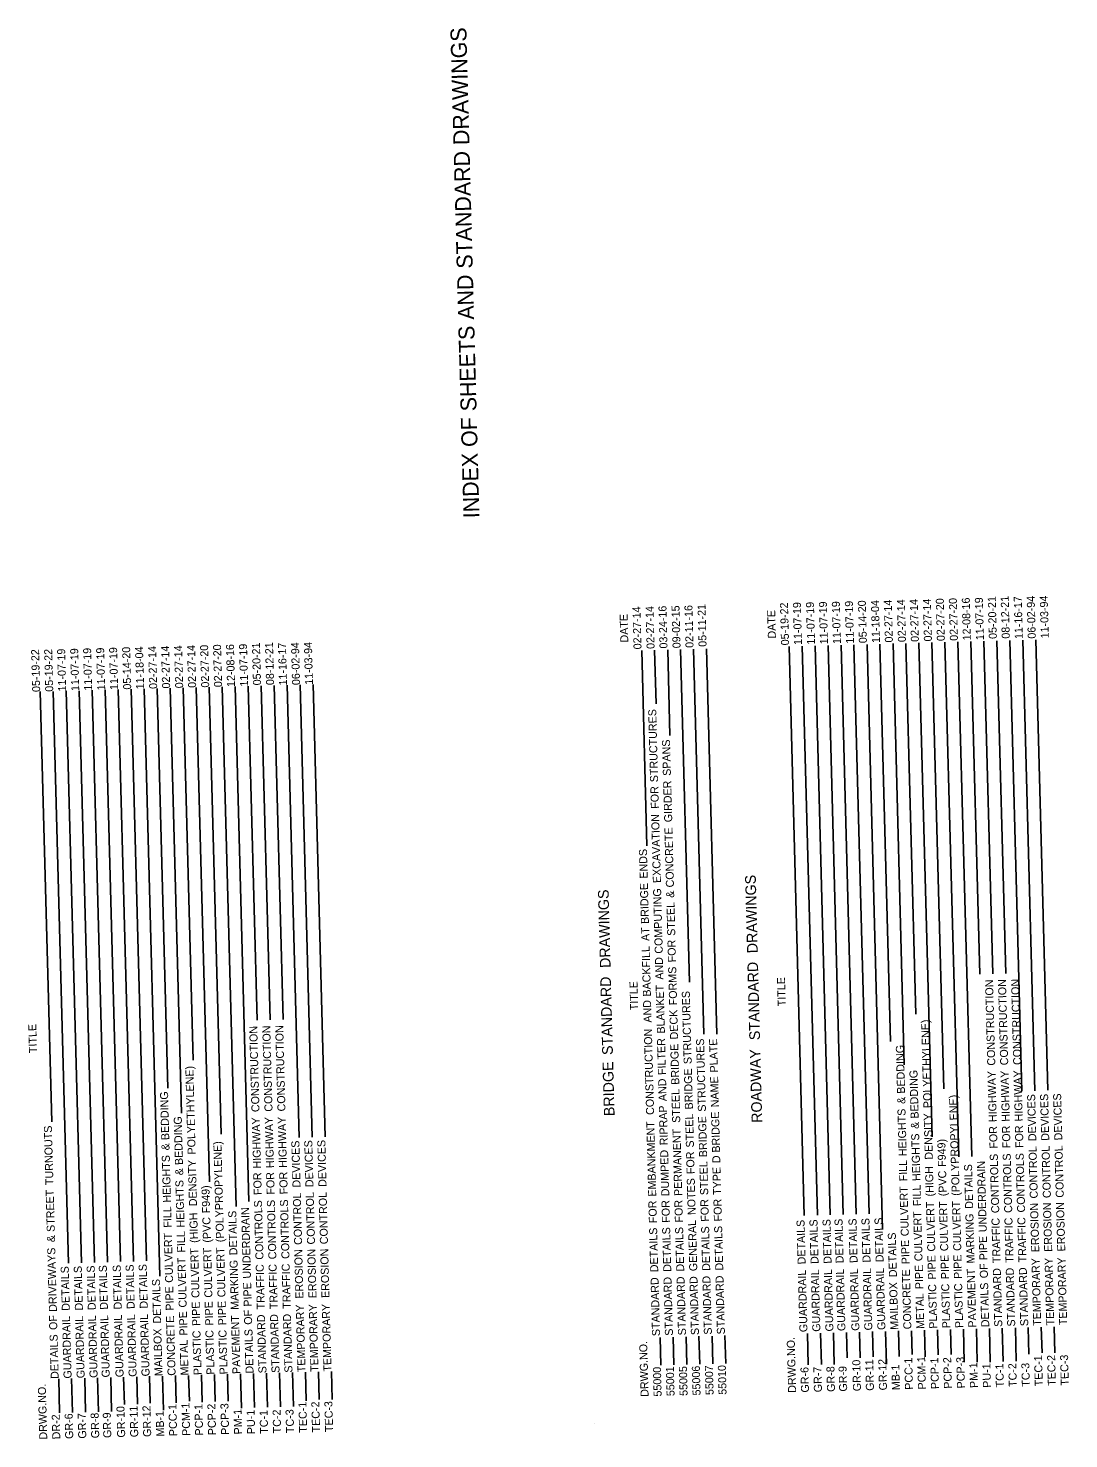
# Model space of a CAD drawing. Extents: x 1930579 to 1932146, y 596452 to 597806.
# Drawn here: x 1931365 to 1932146, y 596748 to 597806 of the extents above; entities that cross this region are included whole.
import ezdxf

# ---------------------------------------------------------------- set-up
doc = ezdxf.new("R2010")
doc.units = 0
doc.layers.add('Default', color=7, linetype='Continuous')
doc.layers.add('R_Annotation', color=7, linetype='Continuous')

msp = doc.modelspace()

# ---------------------------------------------------------------- linework, layer by layer
at = {"layer": 'Default'}
for p, q in [((1931996.5, 596916.5), (1931985, 597343.3)), ((1932006.5, 596904.8), (1931994.8, 597343.5)), ((1932012.5, 597045.6), (1932004.5, 597343.8)), ((1932022.7, 597028.1), (1932014.3, 597344.1)), ((1932031.5, 597066.3), (1932024, 597344.3)), ((1932043.7, 596974.1), (1932033.7, 597344.6)), ((1932052.5, 597010.3), (1932043.5, 597344.9)), ((1932063.6, 596959.1), (1932053.2, 597345.1)), ((1932073.3, 596959.4), (1932063, 597345.4)), ((1932079.4, 597096.1), (1932072.7, 597345.6)), ((1932089.2, 597096.4), (1932082.5, 597345.9)), ((1932098.9, 597096.7), (1932092.2, 597346.2)), ((1932111, 597008.5), (1932102, 597346.4)), ((1932120.8, 597008.8), (1932111.7, 597346.7)), ((1932130.5, 597009.1), (1932121.5, 597346.9)), ((1931829.6, 597192.4), (1931825.7, 597339)), ((1931836.5, 597299), (1931835.4, 597339.3)), ((1931846.9, 597275.2), (1931845.2, 597339.5)), ((1931861.6, 597090.3), (1931854.9, 597339.8)), ((1931872.4, 597051.3), (1931864.6, 597340)), ((1931882.1, 597051.3), (1931874.4, 597340.3)), ((1931947.7, 596915.1), (1931936.3, 597342)), ((1931957.5, 596915.4), (1931946, 597342.2)), ((1931967.2, 596915.7), (1931955.8, 597342.5)), ((1931977, 596915.9), (1931965.5, 597342.8)), ((1931986.7, 596916.2), (1931975.3, 597343)), ((1931501.1, 597311.5), (1931510.1, 596976.2)), ((1931510.9, 597311.7), (1931521.4, 596921.9)), ((1931520.6, 597312), (1931531, 596925.8)), ((1931530.4, 597312.2), (1931537.1, 597061.7)), ((1931540.1, 597312.5), (1931546.9, 597061.9)), ((1931549.9, 597312.8), (1931556.6, 597062.2)), ((1931559.6, 597313), (1931568.7, 596973.6)), ((1931569.4, 597313.3), (1931578.5, 596973.9)), ((1931579.1, 597313.5), (1931588.2, 596974.1)), ((1931374.4, 597308.1), (1931383.1, 596985.5)), ((1931384.2, 597308.3), (1931395.7, 596879.5)), ((1931393.9, 597308.6), (1931405.4, 596879.8)), ((1931403.7, 597308.8), (1931415.2, 596880)), ((1931413.4, 597309.1), (1931424.9, 596880.3)), ((1931423.2, 597309.4), (1931434.7, 596880.6)), ((1931432.9, 597309.6), (1931444.4, 596880.8)), ((1931442.7, 597309.9), (1931454.2, 596881.1)), ((1931452.4, 597310.1), (1931464.2, 596869.8)), ((1931462.2, 597310.4), (1931470.2, 597010.7)), ((1931471.9, 597310.7), (1931480.5, 596992)), ((1931481.7, 597310.9), (1931489.1, 597031.7)), ((1931491.4, 597311.2), (1931501.3, 596940.5)), ((1931879, 596804), (1931878.5, 596824.8)), ((1931888.8, 596804.2), (1931888.2, 596825.1)), ((1931950.7, 596803.2), (1931950.1, 596826.8)), ((1931960.5, 596803.5), (1931959.9, 596827)), ((1931970.2, 596803.4), (1931969.6, 596827.3)), ((1931979.9, 596808.4), (1931979.4, 596827.5)), ((1931989.6, 596808.4), (1931989.1, 596827.8)), ((1931999.3, 596809.3), (1931998.8, 596828.1)), ((1932009.3, 596803.7), (1932008.6, 596828.3)), ((1932018.9, 596809.4), (1932018.3, 596828.6)), ((1932028.6, 596810.9), (1932028.1, 596828.8)), ((1932038.4, 596809.1), (1932037.8, 596829.1)), ((1932048.1, 596810.7), (1932047.6, 596829.4)), ((1932057.8, 596811), (1932057.3, 596829.6)), ((1932067.7, 596805.1), (1932067.1, 596829.9)), ((1932077.5, 596805.2), (1932076.8, 596830.2)), ((1932087.2, 596805.1), (1932086.6, 596830.4)), ((1932097, 596805.8), (1932096.3, 596830.7)), ((1932106.7, 596806), (1932106.1, 596830.9)), ((1932116.3, 596811.3), (1932115.8, 596831.2)), ((1932126.1, 596812.1), (1932125.5, 596831.5)), ((1932135.8, 596812.2), (1932135.3, 596831.7)), ((1931840, 596802.9), (1931839.5, 596823.8)), ((1931849.8, 596803.2), (1931849.2, 596824)), ((1931859.5, 596803.5), (1931859, 596824.3)), ((1931869.3, 596803.7), (1931868.7, 596824.6)), ((1931398, 596793), (1931398.7, 596767.4)), ((1931407.8, 596793.2), (1931408.5, 596767.7)), ((1931417.5, 596793.5), (1931418.2, 596768)), ((1931427.3, 596793.8), (1931427.9, 596768.2)), ((1931437, 596794), (1931437.6, 596773.4)), ((1931446.8, 596794.3), (1931447.3, 596773.7)), ((1931456.5, 596794.6), (1931457, 596774.5)), ((1931466.2, 596794.8), (1931466.9, 596769.3)), ((1931476, 596795.1), (1931476.5, 596774.8)), ((1931485.7, 596795.3), (1931486.3, 596775.9)), ((1931495.5, 596795.6), (1931496, 596775.3)), ((1931505.2, 596795.9), (1931505.8, 596775.6)), ((1931515, 596796.1), (1931515.5, 596775.9)), ((1931524.7, 596796.4), (1931525.4, 596770.8)), ((1931534.5, 596796.7), (1931535.2, 596771.1)), ((1931544.2, 596796.9), (1931544.9, 596771.4)), ((1931554, 596797.2), (1931554.7, 596771.6)), ((1931563.7, 596797.4), (1931564.4, 596771.9)), ((1931573.5, 596797.7), (1931574, 596776.2)), ((1931583.2, 596798), (1931583.8, 596777.1)), ((1931593, 596798.2), (1931593.5, 596777.3)), ((1931388.3, 596792.7), (1931389, 596767.2)), ((1931790.2, 596759.1), (1931790.2, 596759.1))]:
    msp.add_line(p, q, dxfattribs=at)

# ---------------------------------------------------------------- texts
for s, height, p in [('11-07-19', 6, (1931946, 597343.2)), ('11-07-19', 6, (1931955.8, 597343.4)), ('11-07-19', 6, (1931965.5, 597343.7)), ('11-07-19', 6, (1931975.2, 597343.9)), ('11-07-19', 6, (1931985, 597344.2)), ('05-14-20', 6, (1931994.7, 597344.5)), ('11-18-04', 6, (1932004.5, 597344.7)), ('02-27-14', 6, (1932014.2, 597345)), ('02-27-14', 6, (1932024, 597345.3)), ('02-27-14', 6, (1932033.7, 597345.5)), ('02-27-14', 6, (1932043.5, 597345.8)), ('02-27-20', 6, (1932053.2, 597346.1)), ('02-27-20', 6, (1932063, 597346.3)), ('12-08-16', 6, (1932072.7, 597346.6)), ('11-07-19', 6, (1932082.5, 597346.8)), ('05-20-21', 6, (1932092.2, 597347.7)), ('08-12-21', 6, (1932101.9, 597347.9)), ('11-16-17', 6, (1932111.7, 597347.6)), ('06-02-94', 6, (1932121.4, 597347.9)), ('11-03-94', 6, (1932131.2, 597348.1)), ('DATE', 6, (1931815.7, 597345)), ('02-27-14', 6, (1931825.6, 597339.9)), ('02-27-14', 6, (1931835.4, 597340.2)), ('03-24-16', 6, (1931845.1, 597340.5)), ('09-02-15', 6, (1931854.9, 597340.7)), ('02-11-16', 6, (1931864.6, 597341)), ('05-11-21', 6, (1931874.4, 597341.8)), ('DATE', 6, (1931926.4, 597348)), ('05-19-22', 6, (1931936.3, 597342.9)), ('02-27-20', 6, (1931510.9, 597311.5)), ('12-08-16', 6, (1931520.6, 597311.7)), ('11-07-19', 6, (1931530.4, 597312)), ('05-20-21', 6, (1931540.1, 597312.9)), ('08-12-21', 6, (1931549.9, 597313.1)), ('11-16-17', 6, (1931559.6, 597312.8)), ('06-02-94', 6, (1931569.4, 597313.1)), ('11-03-94', 6, (1931579.1, 597313.3)), ('05-19-22', 6, (1931374.4, 597307.9)), ('05-19-22', 6, (1931384.2, 597308.1)), ('11-07-19', 6, (1931393.9, 597308.3)), ('11-07-19', 6, (1931403.7, 597308.6)), ('11-07-19', 6, (1931413.4, 597308.9)), ('11-07-19', 6, (1931423.2, 597309.1)), ('11-07-19', 6, (1931432.9, 597309.4)), ('05-14-20', 6, (1931442.7, 597309.7)), ('11-18-04', 6, (1931452.4, 597309.9)), ('02-27-14', 6, (1931462.2, 597310.2)), ('02-27-14', 6, (1931471.9, 597310.5)), ('02-27-14', 6, (1931481.7, 597310.7)), ('02-27-14', 6, (1931491.4, 597311)), ('02-27-20', 6, (1931501.2, 597311.2)), (' STRUCTURES', 6, (1931838.1, 597238)), (' SPANS', 6, (1931847.7, 597242.8)), (' GIRDER', 6, (1931848.7, 597208)), (' FOR', 6, (1931838.7, 597218.1)), (' EXCAVATION', 6, (1931840.2, 597162.4)), (' CONCRETE', 6, (1931850, 597159.1)), (' ENDS', 6, (1931830.3, 597165.7)), (' BRIDGE', 6, (1931831.2, 597131.7)), (' DRAWINGS', 8, (1931912.9, 597109)), (' DRAWINGS', 8, (1931802.5, 597098)), (' COMPUTING', 6, (1931841.6, 597109.4)), (' &', 6, (1931850.2, 597151.3)), (' STEEL', 6, (1931851, 597122.8)), (' AT', 6, (1931831.6, 597118.9)), (' FOR', 6, (1931851.5, 597102.9)), (' BACKFILL', 6, (1931832.7, 597077.2)), (' AND', 6, (1931842.1, 597089.9)), (' FORMS', 6, (1931852.4, 597070.7)), (' STANDARD', 8, (1931914.6, 597043.8)), (' STANDARD', 8, (1931804.2, 597032.7)), ('TITLE', 6, (1931823.1, 597069.2)), ('TITLE', 6, (1931933.8, 597072.2)), (' CONSTRUCTION', 6, (1932091.1, 597025.4)), (' CONSTRUCTION', 6, (1932100.8, 597025.7)), (' CONSTRUCTION', 6, (1932110.6, 597025.9)), (' BLANKET', 6, (1931843.2, 597049.5)), (' STRUCTURES', 6, (1931863.3, 597026.6)), (' AND', 6, (1931833.2, 597057.7)), (' DECK', 6, (1931853.1, 597045.1)), ('TITLE', 6, (1931372, 597037.1)), (' POLYETHYLENE)', 6, (1932043.2, 596993.6)), (' CONSTRUCTION', 6, (1931539, 596990.6)), (' CONSTRUCTION', 6, (1931548.8, 596990.9)), (' CONSTRUCTION', 6, (1931558.5, 596991.1)), (' CONSTRUCTION', 6, (1931835.1, 596988.5)), (' FILTER', 6, (1931844, 597018.4)), (' STRUCTURES', 6, (1931874, 596990.9)), (' PLATE', 6, (1931883, 597020.3)), (' BRIDGE', 6, (1931854, 597011.1)), ('ROADWAY', 8, (1931916.2, 596984.8)), (' BEDDING', 6, (1932023.4, 597004.4)), (' POLYETHYLENE)', 6, (1931491.1, 596958.8)), ('BRIDGE', 8, (1931805.4, 596989.8)), (' AND', 6, (1931844.5, 596998.8)), (' BRIDGE', 6, (1931864.2, 596992.6)), (' NAME', 6, (1931883.7, 596994.2)), (' BEDDING', 6, (1932033.6, 596985.7)), (' HIGHWAY', 6, (1932092.2, 596983.1)), (' HIGHWAY', 6, (1932102, 596983.4)), (' HIGHWAY', 6, (1932111.7, 596983.6)), (' BEDDING', 6, (1931471.3, 596969.6)), (' STEEL', 6, (1931854.7, 596982.5)), (' (POLYPROPYLENE)', 6, (1932064.4, 596927.8)), (' DEVICES', 6, (1932121.9, 596968.8)), (' DEVICES', 6, (1932131.6, 596969.1)), (' DEVICES', 6, (1932141.4, 596969.4)), (' RIPRAP', 6, (1931845.4, 596965.7)), (' &', 6, (1932023.6, 596996.7)), (' HEIGHTS', 6, (1932024.6, 596957.5)), (' BEDDING', 6, (1931481.6, 596950.9)), (' HIGHWAY', 6, (1931540.2, 596948.3)), (' HIGHWAY', 6, (1931549.9, 596948.6)), (' HIGHWAY', 6, (1931559.6, 596948.8)), (' EMBANKMENT', 6, (1931836.7, 596927.2)), (' STEEL', 6, (1931865, 596964)), (' BRIDGE', 6, (1931874.9, 596956.8)), (' BRIDGE', 6, (1931884.6, 596960.2)), (' &', 6, (1932033.8, 596978)), ('  DENSITY', 6, (1932044.3, 596952.7)), (' TURNOUTS', 6, (1931384.4, 596935.9)), (' PERMANENT', 6, (1931856.2, 596927.7)), (' HEIGHTS', 6, (1932034.9, 596938.9)), (' FOR', 6, (1932092.8, 596963.2)), (' FOR', 6, (1932102.5, 596963.5)), (' FOR', 6, (1932112.2, 596963.7)), (' &', 6, (1931471.5, 596961.9)), (' (POLYPROPYLENE)', 6, (1931512.4, 596893)), (' DEVICES', 6, (1931569.8, 596934)), (' DEVICES', 6, (1931579.5, 596934.3)), (' DEVICES', 6, (1931589.3, 596934.5)), (' DUMPED', 6, (1931846.5, 596927.5)), (' FOR', 6, (1931865.5, 596944.1)), (' F949)', 6, (1932054.1, 596949.5)), (' CONTROL', 6, (1932123, 596925.8)), (' CONTROL', 6, (1932132.8, 596926.1)), (' CONTROL', 6, (1932142.5, 596926.4)), (' HEIGHTS', 6, (1931472.6, 596922.7)), ('  DENSITY', 6, (1931492.2, 596917.8)), (' STEEL', 6, (1931875.7, 596928.3)), (' D', 6, (1931884.8, 596952.3)), (' FILL', 6, (1932025.1, 596938.7)), (' DETAILS', 6, (1932074.5, 596918.1)), (' UNDERDRAIN', 6, (1932084.7, 596900.5)), (' CONTROLS', 6, (1932094.1, 596914.8)), (' CONTROLS', 6, (1932103.8, 596915)), (' CONTROLS', 6, (1932113.5, 596915.3)), (' &', 6, (1931481.8, 596943.2)), (' HEIGHTS', 6, (1931482.8, 596904)), (' FOR', 6, (1931540.7, 596928.4)), (' FOR', 6, (1931550.4, 596928.7)), (' FOR', 6, (1931560.2, 596928.9)), (' NOTES', 6, (1931866.3, 596913.4)), (' TYPE', 6, (1931885.4, 596928.5)), (' (HIGH', 6, (1932044.9, 596927.3)), (' (PVC', 6, (1932054.7, 596927.5)), (' STREET', 6, (1931385.4, 596900.7)), (' F949)', 6, (1931502, 596914.7)), (' CONTROL', 6, (1931571, 596891)), (' CONTROL', 6, (1931580.7, 596891.3)), (' CONTROL', 6, (1931590.4, 596891.5)), (' CULVERT', 6, (1932026.2, 596897.5)), (' FILL', 6, (1932035.4, 596920.1)), (' FILL', 6, (1931473.1, 596903.9)), (' UNDERDRAIN', 6, (1931532.6, 596865.7)), (' CONTROLS', 6, (1931542, 596879.9)), (' CONTROLS', 6, (1931551.7, 596880.2)), (' CONTROLS', 6, (1931561.5, 596880.5)), (' FOR', 6, (1931837.2, 596907.3)), (' FOR', 6, (1931847, 596907.6)), (' FOR', 6, (1931856.7, 596907.8)), (' FOR', 6, (1931876.2, 596908.4)), (' FOR', 6, (1931886, 596908.6)), (' CULVERT', 6, (1932046.1, 596886)), (' CULVERT', 6, (1932055.8, 596886.3)), (' CULVERT', 6, (1932065.6, 596886.5)), (' EROSION', 6, (1932124.1, 596885.5)), (' EROSION', 6, (1932133.8, 596885.8)), (' EROSION', 6, (1932143.6, 596886.1)), (' (HIGH', 6, (1931492.9, 596892.5)), (' (PVC', 6, (1931502.6, 596892.7)), (' DETAILS', 6, (1931522.4, 596883.2)), (' GENERAL', 6, (1931867.5, 596871.3)), (' DETAILS', 6, (1931948.8, 596876.4)), (' DETAILS', 6, (1931958.5, 596876.7)), (' DETAILS', 6, (1931968.3, 596876.9)), (' DETAILS', 6, (1931977.3, 596877.2)), (' DETAILS', 6, (1931987.8, 596877.4)), (' DETAILS', 6, (1931997.5, 596877.7)), (' DETAILS', 6, (1932007.3, 596878)), (' CULVERT', 6, (1932036.5, 596878.8)), (' MARKING', 6, (1932075.6, 596877.1)), (' TRAFFIC', 6, (1932095.1, 596877.4)), (' TRAFFIC', 6, (1932104.8, 596877.6)), (' TRAFFIC', 6, (1932114.5, 596877.9)), (' &', 6, (1931385.6, 596893)), (' CULVERT', 6, (1931474.2, 596862.6)), (' FILL', 6, (1931483.3, 596885.2)), (' DETAILS', 6, (1931838.2, 596870.5)), (' DETAILS', 6, (1931848, 596870.8)), (' DETAILS', 6, (1931857.7, 596871)), (' DETAILS', 6, (1931877.2, 596871.5)), (' DETAILS', 6, (1931887, 596871.8)), (' DETAILS', 6, (1932017.3, 596866.8)), (' PIPE', 6, (1932085.2, 596879.5)), (' DRIVEWAYS', 6, (1931387, 596840.8)), (' CULVERT', 6, (1931494, 596851.2)), (' CULVERT', 6, (1931503.7, 596851.4)), (' CULVERT', 6, (1931513.5, 596851.7)), (' EROSION', 6, (1931572, 596850.7)), (' EROSION', 6, (1931581.8, 596851)), (' EROSION', 6, (1931591.5, 596851.2)), (' PIPE', 6, (1932026.8, 596876.5)), (' DETAILS', 6, (1931425.3, 596842.4)), (' DETAILS', 6, (1931435.7, 596842.6)), (' DETAILS', 6, (1931445.4, 596842.9)), (' DETAILS', 6, (1931455.2, 596843.2)), (' CULVERT', 6, (1931484.4, 596844)), (' MARKING', 6, (1931523.5, 596842.3)), (' TRAFFIC', 6, (1931543, 596842.6)), (' TRAFFIC', 6, (1931552.7, 596842.8)), (' TRAFFIC', 6, (1931562.5, 596843.1)), (' PIPE', 6, (1932037.1, 596857.8)), (' PIPE', 6, (1932046.6, 596865)), (' PIPE', 6, (1932056.4, 596865.3)), (' PIPE', 6, (1932066.1, 596865.5)), (' OF', 6, (1932085.6, 596866)), ('TEMPORARY', 6, (1932125.5, 596832.5)), ('TEMPORARY', 6, (1932135.3, 596832.8)), ('TEMPORARY', 6, (1932145, 596833)), (' DETAILS', 6, (1931396.7, 596841.6)), (' DETAILS', 6, (1931406.5, 596841.8)), (' DETAILS', 6, (1931416.2, 596842.1)), (' DETAILS', 6, (1931465.2, 596832)), ('STANDARD', 6, (1931839.5, 596824.8)), ('STANDARD', 6, (1931849.2, 596825.1)), ('STANDARD', 6, (1931859, 596825.4)), ('STANDARD', 6, (1931868.7, 596825.6)), ('STANDARD', 6, (1931878.4, 596825.9)), ('STANDARD', 6, (1931888.2, 596826.1)), ('GUARDRAIL', 6, (1931950.1, 596827.8)), ('GUARDRAIL', 6, (1931959.8, 596828.1)), ('GUARDRAIL', 6, (1931969.6, 596828.3)), ('GUARDRAIL', 6, (1931978.6, 596828.6)), ('GUARDRAIL', 6, (1931989.1, 596828.8)), ('GUARDRAIL', 6, (1931998.8, 596829.1)), ('GUARDRAIL', 6, (1932008.6, 596829.4)), ('CONCRETE', 6, (1932028.1, 596829.9)), ('PAVEMENT', 6, (1932076.8, 596831.2)), ('STANDARD', 6, (1932096.3, 596831.7)), ('STANDARD', 6, (1932106, 596832)), ('STANDARD', 6, (1932115.8, 596832.3)), (' PIPE', 6, (1931474.7, 596841.7)), (' PIPE', 6, (1931533.2, 596844.7)), ('MAILBOX', 6, (1932018.3, 596829.6)), ('METAL', 6, (1932037.8, 596830.2)), ('PLASTIC', 6, (1932047.5, 596830.4)), ('PLASTIC', 6, (1932057.3, 596830.7)), ('PLASTIC', 6, (1932067, 596830.9)), ('DETAILS', 6, (1932086.5, 596831.5)), (' PIPE', 6, (1931494.6, 596830.2)), (' PIPE', 6, (1931504.3, 596830.5)), (' PIPE', 6, (1931514.1, 596830.7)), ('TEMPORARY', 6, (1931573.5, 596797.7)), ('TEMPORARY', 6, (1931583.2, 596798)), ('TEMPORARY', 6, (1931593, 596798.2)), (' OF', 6, (1931387.3, 596827.2)), ('GUARDRAIL', 6, (1931398, 596793)), ('GUARDRAIL', 6, (1931407.8, 596793.2)), ('GUARDRAIL', 6, (1931417.5, 596793.5)), ('GUARDRAIL', 6, (1931426.6, 596793.8)), ('GUARDRAIL', 6, (1931437, 596794)), ('GUARDRAIL', 6, (1931446.8, 596794.3)), ('GUARDRAIL', 6, (1931456.5, 596794.6)), ('CONCRETE', 6, (1931476, 596795.1)), (' PIPE', 6, (1931485, 596823)), ('PAVEMENT', 6, (1931524.7, 596796.4)), (' OF', 6, (1931533.5, 596831.1)), ('STANDARD', 6, (1931544.2, 596796.9)), ('STANDARD', 6, (1931554, 596797.2)), ('STANDARD', 6, (1931563.7, 596797.4)), ('DETAILS', 6, (1931388.3, 596792.7)), ('MAILBOX', 6, (1931466.2, 596794.8)), ('PLASTIC', 6, (1931495.5, 596795.6)), ('PLASTIC', 6, (1931505.2, 596795.9)), ('PLASTIC', 6, (1931515, 596796.1)), ('DETAILS', 6, (1931534.5, 596796.7)), ('METAL', 6, (1931485.7, 596795.3)), ('DRWG.NO.', 6, (1931830.9, 596779.3)), ('DRWG.NO.', 6, (1931941.6, 596782.3)), ('GR-10', 6, (1931990.3, 596783.5)), ('GR-11', 6, (1932000, 596783.8)), ('GR-12', 6, (1932009.8, 596784.1)), ('PCC-1', 6, (1932029.3, 596784.6)), ('PCM-1', 6, (1932039, 596784.8)), ('PCP-1', 6, (1932048.8, 596785.1)), ('PCP-2', 6, (1932058.5, 596785.4)), ('PCP-3', 6, (1932068.3, 596785.6)), ('PM-1', 6, (1932078, 596785.9)), ('PU-1', 6, (1932087.8, 596786.1)), ('TC-1', 6, (1932097.5, 596786.4)), ('TC-2', 6, (1932107.2, 596786.7)), ('TC-3', 6, (1932117, 596786.9)), ('TEC-1', 6, (1932126.7, 596787.2)), ('TEC-2', 6, (1932136.5, 596787.5)), ('TEC-3', 6, (1932146.2, 596787.7)), ('55000', 6, (1931840.7, 596779.5)), ('55001', 6, (1931850.4, 596779.8)), ('55005', 6, (1931860.2, 596780)), ('55006', 6, (1931869.9, 596780.3)), ('55007', 6, (1931879.7, 596780.6)), ('55010', 6, (1931889.4, 596780.8)), ('GR-6', 6, (1931951.3, 596782.5)), ('GR-7', 6, (1931961, 596782.7)), ('GR-8', 6, (1931970.8, 596783)), ('GR-9', 6, (1931979.9, 596783.2)), ('MB-1', 6, (1932019.5, 596784.3)), ('DRWG.NO.', 6, (1931379.7, 596747.2)), ('GR-10', 6, (1931438.2, 596748.7)), ('GR-11', 6, (1931448, 596749)), ('GR-12', 6, (1931457.7, 596749.2)), ('PCC-1', 6, (1931477.2, 596749.8)), ('PCM-1', 6, (1931487, 596750)), ('PCP-1', 6, (1931496.7, 596750.3)), ('PCP-2', 6, (1931506.4, 596750.5)), ('PCP-3', 6, (1931516.2, 596750.8)), ('TEC-1', 6, (1931574.7, 596752.4)), ('TEC-2', 6, (1931584.4, 596752.6)), ('TEC-3', 6, (1931594.2, 596752.9)), ('DR-2', 6, (1931389.5, 596747.4)), ('GR-6', 6, (1931399.2, 596747.7)), ('GR-7', 6, (1931409, 596747.9)), ('GR-8', 6, (1931418.7, 596748.2)), ('GR-9', 6, (1931427.8, 596748.4)), ('MB-1', 6, (1931467.5, 596749.5)), ('PM-1', 6, (1931525.9, 596751.1)), ('PU-1', 6, (1931535.7, 596751.3)), ('TC-1', 6, (1931545.4, 596751.6)), ('TC-2', 6, (1931555.2, 596751.9)), ('TC-3', 6, (1931564.9, 596752.1))]:
    msp.add_text(s, height=height, rotation=91.5377, dxfattribs=at).set_placement(p)
at = {"layer": 'R_Annotation'}
msp.add_text('INDEX OF SHEETS AND STANDARD DRAWINGS', height=12, rotation=91.5377, dxfattribs=at).set_placement((1931704, 597438.3))

doc.saveas('drawing.dxf')
